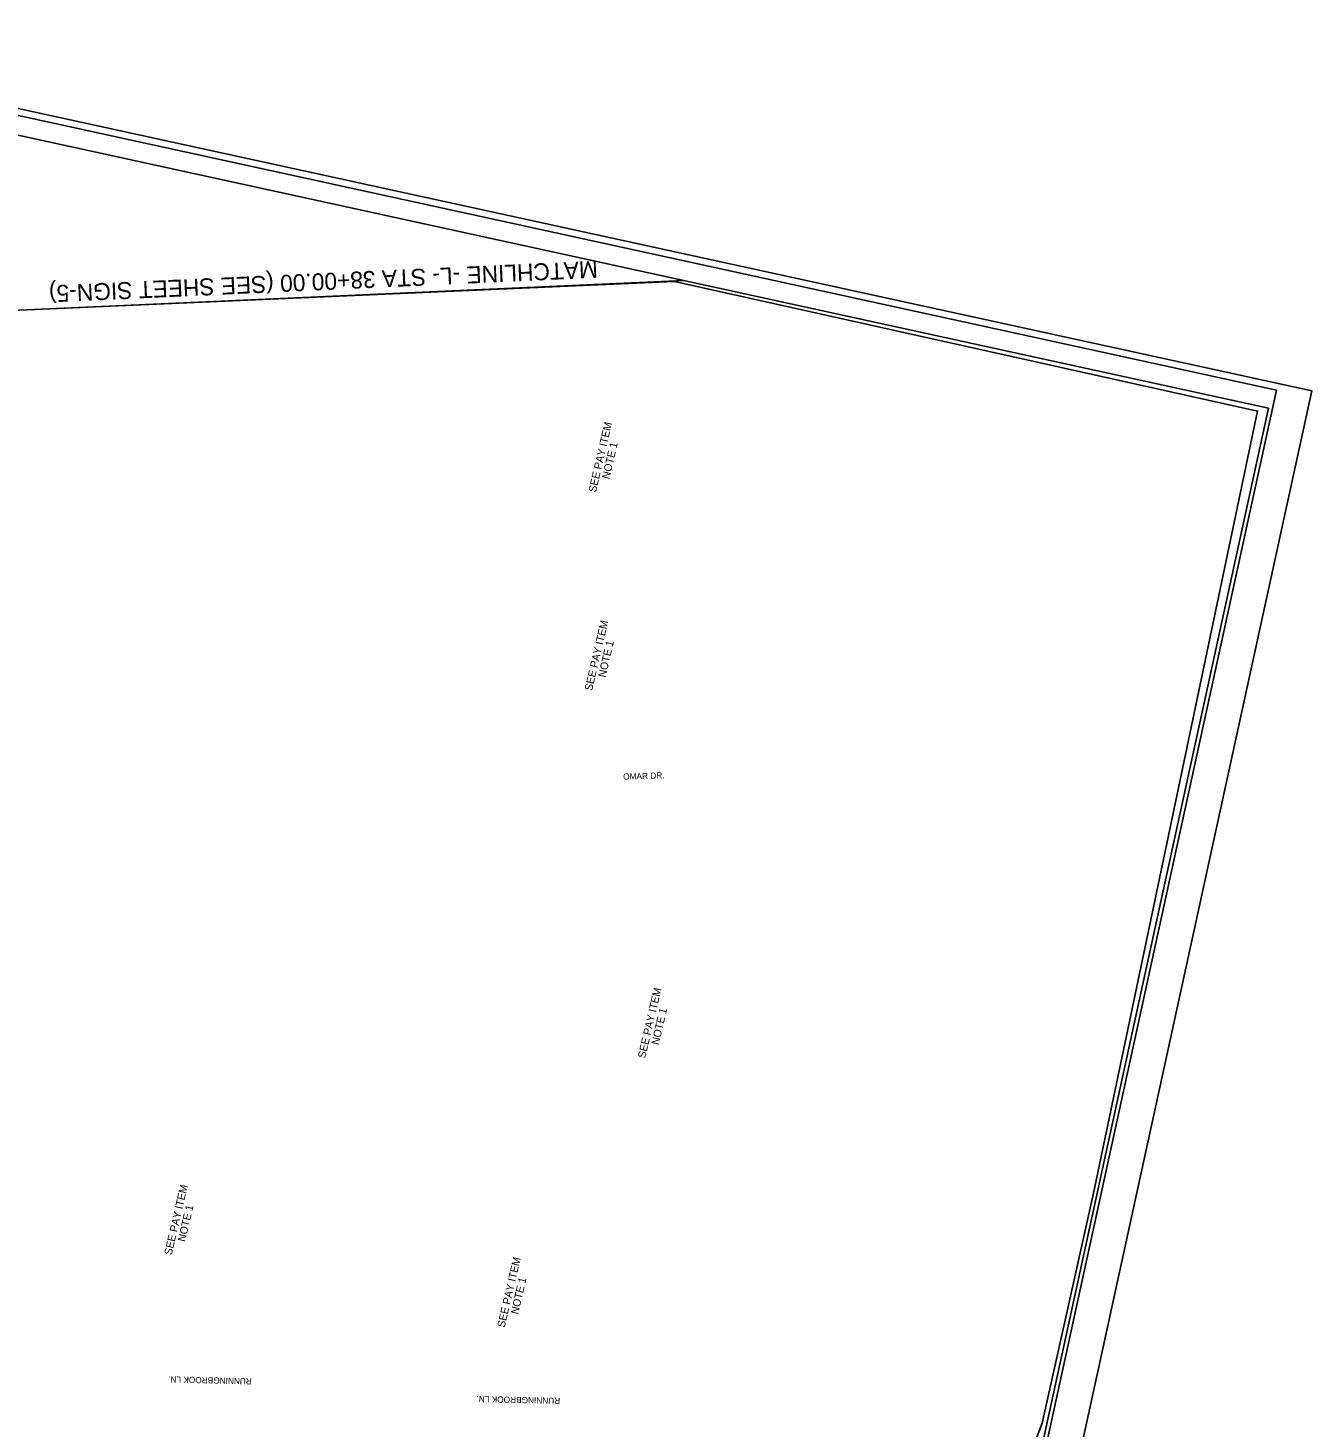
# Model space of a CAD drawing. Extents: x 1615829 to 1617263, y 900664 to 902544.
# Drawn here: x 1616433 to 1617263, y 901639 to 902544 of the extents above; entities that cross this region are included whole.
import ezdxf

# ---------------------------------------------------------------- set-up
doc = ezdxf.new("R2010")
doc.units = 0
for name, color, linetype in [('CTL Primary Horizontal and Vertical CELL', 7, 'Continuous'), ('CTL Primary Horizontal and Vertical Cogo Number', 7, 'Continuous'), ('CTL Secondary Horizontal and Vertical CELL', 7, 'Continuous'), ('Default', 7, 'Continuous'), ('Exist DTM Crownline Cogo Number', 7, 'Continuous'), ('Exist Roads Curbs Cogo Number', 7, 'Continuous'), ('Exist Roads Curbs Cogo Point CELL', 7, 'Continuous'), ('Exist Utilities Sanitary Sewer Manhole CELL', 7, 'Continuous')]:
    doc.layers.add(name, color=color, linetype=linetype)

msp = doc.modelspace()

# ---------------------------------------------------------------- linework, layer by layer
at = {"layer": 'CTL Primary Horizontal and Vertical CELL'}
msp.add_lwpolyline([(1616208.96, 902534.66), (1615853.55, 900906.5), (1616884.38, 900681.48), (1617239.79, 902309.64)], close=True, dxfattribs=at)
at = {"layer": 'CTL Primary Horizontal and Vertical Cogo Number'}
msp.add_lwpolyline([(1616187.99, 902543.84), (1615828.85, 900898.58), (1616903.54, 900663.99), (1617262.68, 902309.25)], close=True, dxfattribs=at)
at = {"layer": 'CTL Secondary Horizontal and Vertical CELL'}
msp.add_lwpolyline([(1616208.79, 902521.9), (1615888.89, 901056.41), (1616914.73, 900832.48), (1617234.63, 902297.97)], close=True, dxfattribs=at)
at = {"layer": 'Exist DTM Crownline Cogo Number'}
msp.add_lwpolyline([(1616850.42, 902379.94), (1617227.49, 902296.2), (1617121.36, 901790.43), (1617088.18, 901641.75), (1617042.44, 901522.26), (1617032.35, 901430.63), (1617021.35, 901334.38), (1616928.77, 900896.77), (1615902.83, 901120.28), (1615974.27, 901386.7), (1616087.67, 901888.92), (1616145.49, 901879.24), (1616184.12, 901827.49), (1616138.37, 901614.97), (1616150.59, 901618.07), (1616181.32, 901620.66), (1616299.19, 901764.2), (1616120.07, 901933.32), (1616161.35, 902112.51), (1616179.69, 902310.42), (1616356.27, 902284.95), (1616372.44, 902359.01)], close=True, dxfattribs=at)
at = {"layer": 'Exist Roads Curbs Cogo Point CELL'}
msp.add_line((1616372.44, 902359.01), (1616856.51, 902380.51), dxfattribs=at)

# ---------------------------------------------------------------- texts
at = {"layer": 'Default'}
for s, p in [('SEE PAY ITEM', (1616799.64, 902243.24)), ('NOTE 1', (1616808.38, 902251.86)), ('SEE PAY ITEM', (1616797.17, 902114.99)), ('NOTE 1', (1616805.9, 902123.62)), ('SEE PAY ITEM', (1616831.56, 901877.43)), ('NOTE 1', (1616840.3, 901886.06)), ('SEE PAY ITEM', (1616525.36, 901750.14)), ('NOTE 1', (1616534.09, 901758.76)), ('SEE PAY ITEM', (1616740.65, 901703.26)), ('NOTE 1', (1616749.38, 901711.88))]:
    msp.add_text(s, height=5, rotation=76.89482, dxfattribs=at).set_placement(p)
at = {"layer": 'Exist Roads Curbs Cogo Number'}
msp.add_text('MATCHLINE -L- STA 38+00.00 (SEE SHEET SIGN-5)', height=11, rotation=182.58128, dxfattribs=at).set_placement((1616800.67, 902393.39))
at = {"layer": 'Exist Utilities Sanitary Sewer Manhole CELL'}
for s, rotation, p in [('OMAR DR.', 1.81778, (1616817.38, 902057.82)), ('RUNNINGBROOK LN.', 178.628, (1616577.26, 901670.83)), ('RUNNINGBROOK LN.', 178.628, (1616776.63, 901658.16))]:
    msp.add_text(s, height=4, rotation=rotation, dxfattribs=at).set_placement(p)

doc.saveas('drawing.dxf')
